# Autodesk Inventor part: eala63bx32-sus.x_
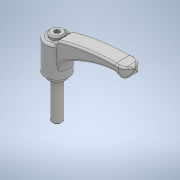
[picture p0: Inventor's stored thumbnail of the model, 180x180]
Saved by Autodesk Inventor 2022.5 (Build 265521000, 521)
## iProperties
Created: 2018-05
Part Number: eala63bx32-sus.x_
Material: 一般
Document SubType Name: Modeling
Designer: imaocorp
Density: 1 g/cm^3
Appearance: 既定
Sending System: SOLIDWORKS 2016-2016286
MC: AMD64
MC_MODEL: AMD64 Family 21 Model 2 Stepping 0, AuthenticAMD
OS: Windows_NT
FRU: Parasolid Version 28.0, build 224,  7-29-2016
FORMAT: text
GUISE: transmit
KEY: eala63bx32-sus
FILE: eala63bx32-sus.x_t
DATE: Fri May 18 11:30:36 2018
Author: imaocorp
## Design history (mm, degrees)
feature "Base1"
node "ソリッド1"
